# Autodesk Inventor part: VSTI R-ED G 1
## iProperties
Shininess: 25.0
Length Units: 11269
Angle Units: 11279
Time Units: 11290
Mass Units: 11283
Length Display Precision: 3
Angle Display Precision: 2
Created: 2002-11
Part Number: VSTI R-ED G 1
Material: 1.0037 St 37-2
Description: blanking plug for port
Document SubType Name: Modellieren
Designer: hs
Density: 0.0
Volumn: 0.0
Area: 0.0
PropertySet Name: Model Information
Control State: 0
Master: False
Checked Out: False
Title: VSTI G 1
Author: hs
Keywords: VSTI R 3-8
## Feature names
1. Drehung1 [Revolution]
2. Rundung3 [Fillet]
3. Fase1 [Chamfer]
4. Bohrung1 [Hole]
5. Fase2 [Chamfer]
6. Extrusion2
7. Fase3 [Chamfer]
8. Drehung2 [Revolution]
9. Drehung3 [Revolution]
